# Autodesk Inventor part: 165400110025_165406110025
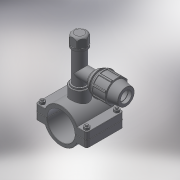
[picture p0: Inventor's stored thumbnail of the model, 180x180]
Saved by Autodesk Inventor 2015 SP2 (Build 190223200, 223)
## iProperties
Created: 2017-05
Part Number: 165400110025_165406110025
Material: Generic
Description: PLASSON TAPPER FOR PE+PVC PIPE 110-25
Document SubType Name: Modeling
Designer: KIM
Density: 1 g/cm^3
Appearance: Default
Author: KIM
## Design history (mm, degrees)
derived "16540.ipt"
feature "Solid1::16540.ipt"
feature "Solid2::16540.ipt"
tag "TaggingFeature1"
body "Solid1"
other parameters: "d0" = 121, "d1" = 165, "d2" = 55, "d4" = 116, "d5" = 0, "d6" = 8.25, "d7" = 165, "d8" = 0.1, "d10" = 0, "d11" = 1.1, "d14" = 39.3783, "d20" = 1.1, "d23" = 1.1, "d36" = 13, "d37" = 10.4, "d38" = 63, "d39" = 0, "d40" = 3, "d41" = 5, "d42" = 0, "d43" = 8, "d44" = 3, "d45" = 0, "d46" = 1.1, "d51" = 87, "d52" = 30.291, "d53" = 21, "d54" = 0, "d55" = 25, "d57" = 0, "d58" = 118.8, "d60" = 0, "d62" = 13, "d63" = 10.4, "d66" = 95.2, "d67" = 25, "d68" = 8.75, "d69" = 21, "d70" = 54, "d71" = 40.5, "d72" = 1.5, "d73" = 43.2, "d74" = 120 deg, "d75" = 37.5, "d76" = 10 deg, "d77" = 48.6, "d78" = 31.5, "d79" = 61, "d81" = 105, "d82" = 6.1, "d87" = 15, "d90" = 50.22, "d91" = 35 deg, "d92" = 17.5 deg, "d94" = 0, "d96" = 360 deg, "d98" = 0.5, "d99" = 67.1, "d100" = 27.2619, "d101" = 135 deg, "d102" = 1.08, "d105" = 2.7, "d106" = 0, "d107" = 0.1, "d108" = 27.2619, "d109" = 33.3201, "d111" = 26.4, "d112" = 6.6, "d113" = 3.5, "d116" = 0, "d118" = 21, "d119" = 0, "d121" = 132, "d122" = 59, "B_" = 25, "G_" = 30.291, "A_" = 87, "L_" = 165, "L_1" = 116, "l_2" = 21, "d_1" = 25, "E_" = 54, "l_" = 61, "H_" = 105, "H_1" = 59, "H_2" = 132
